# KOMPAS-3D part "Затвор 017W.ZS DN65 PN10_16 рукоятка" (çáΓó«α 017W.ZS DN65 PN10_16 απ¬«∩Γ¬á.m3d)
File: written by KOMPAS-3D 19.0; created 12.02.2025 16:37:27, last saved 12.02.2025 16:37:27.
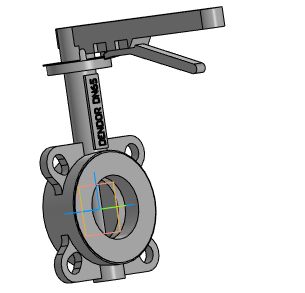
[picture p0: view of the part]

Document properties: Автор: Евгений; Полное имя файла: Затвор 017W.ZS DN65 PN10_16 рукоятка.a3d

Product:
- Part/product: Затвор 017W.ZS DN65 PN10_16 рукоятка
    Масса: 5.36711

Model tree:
1. Операция без истории:1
